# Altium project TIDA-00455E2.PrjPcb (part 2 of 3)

## Sheet Deserializer.SchDoc: Deserializer
size 431 x 279 mm; Date: Not shown in title block; ApprovedBy: Not shown in title block; CheckedBy: Not shown in title block; Author: Not shown in title block; CompanyName: Not shown in title block; DrawnBy: Brian Shaffer; Engineer: Not shown in title block; Organization: Not shown in title block; Address1: Not shown in title block; Address2: Not shown in title block; Address3: Not shown in title block; Address4: Not shown in title block; DocumentNumber: 5; Revision: Use project parameter SCH_Rev; SheetNumber: 5; SheetTotal: 10; PageSetup: Record=PageOptions¦CenterHorizontal=True¦CenterVertical=True¦PrintScale=0.96¦XCorrection=1.00¦YCorrection=1.00¦PrintKind=0¦BorderSize=5000000¦LeftOffset=0¦BottomOffset=0¦Orientation=2¦PaperLength=1000¦PaperWidth=1000¦Scale=100¦PaperSource=15¦PrintQuality=600¦MediaType=1¦DitherType=10¦PrintScaleMode=1¦PaperKind=Tabloid (11 x 17")¦PaperIndex=17
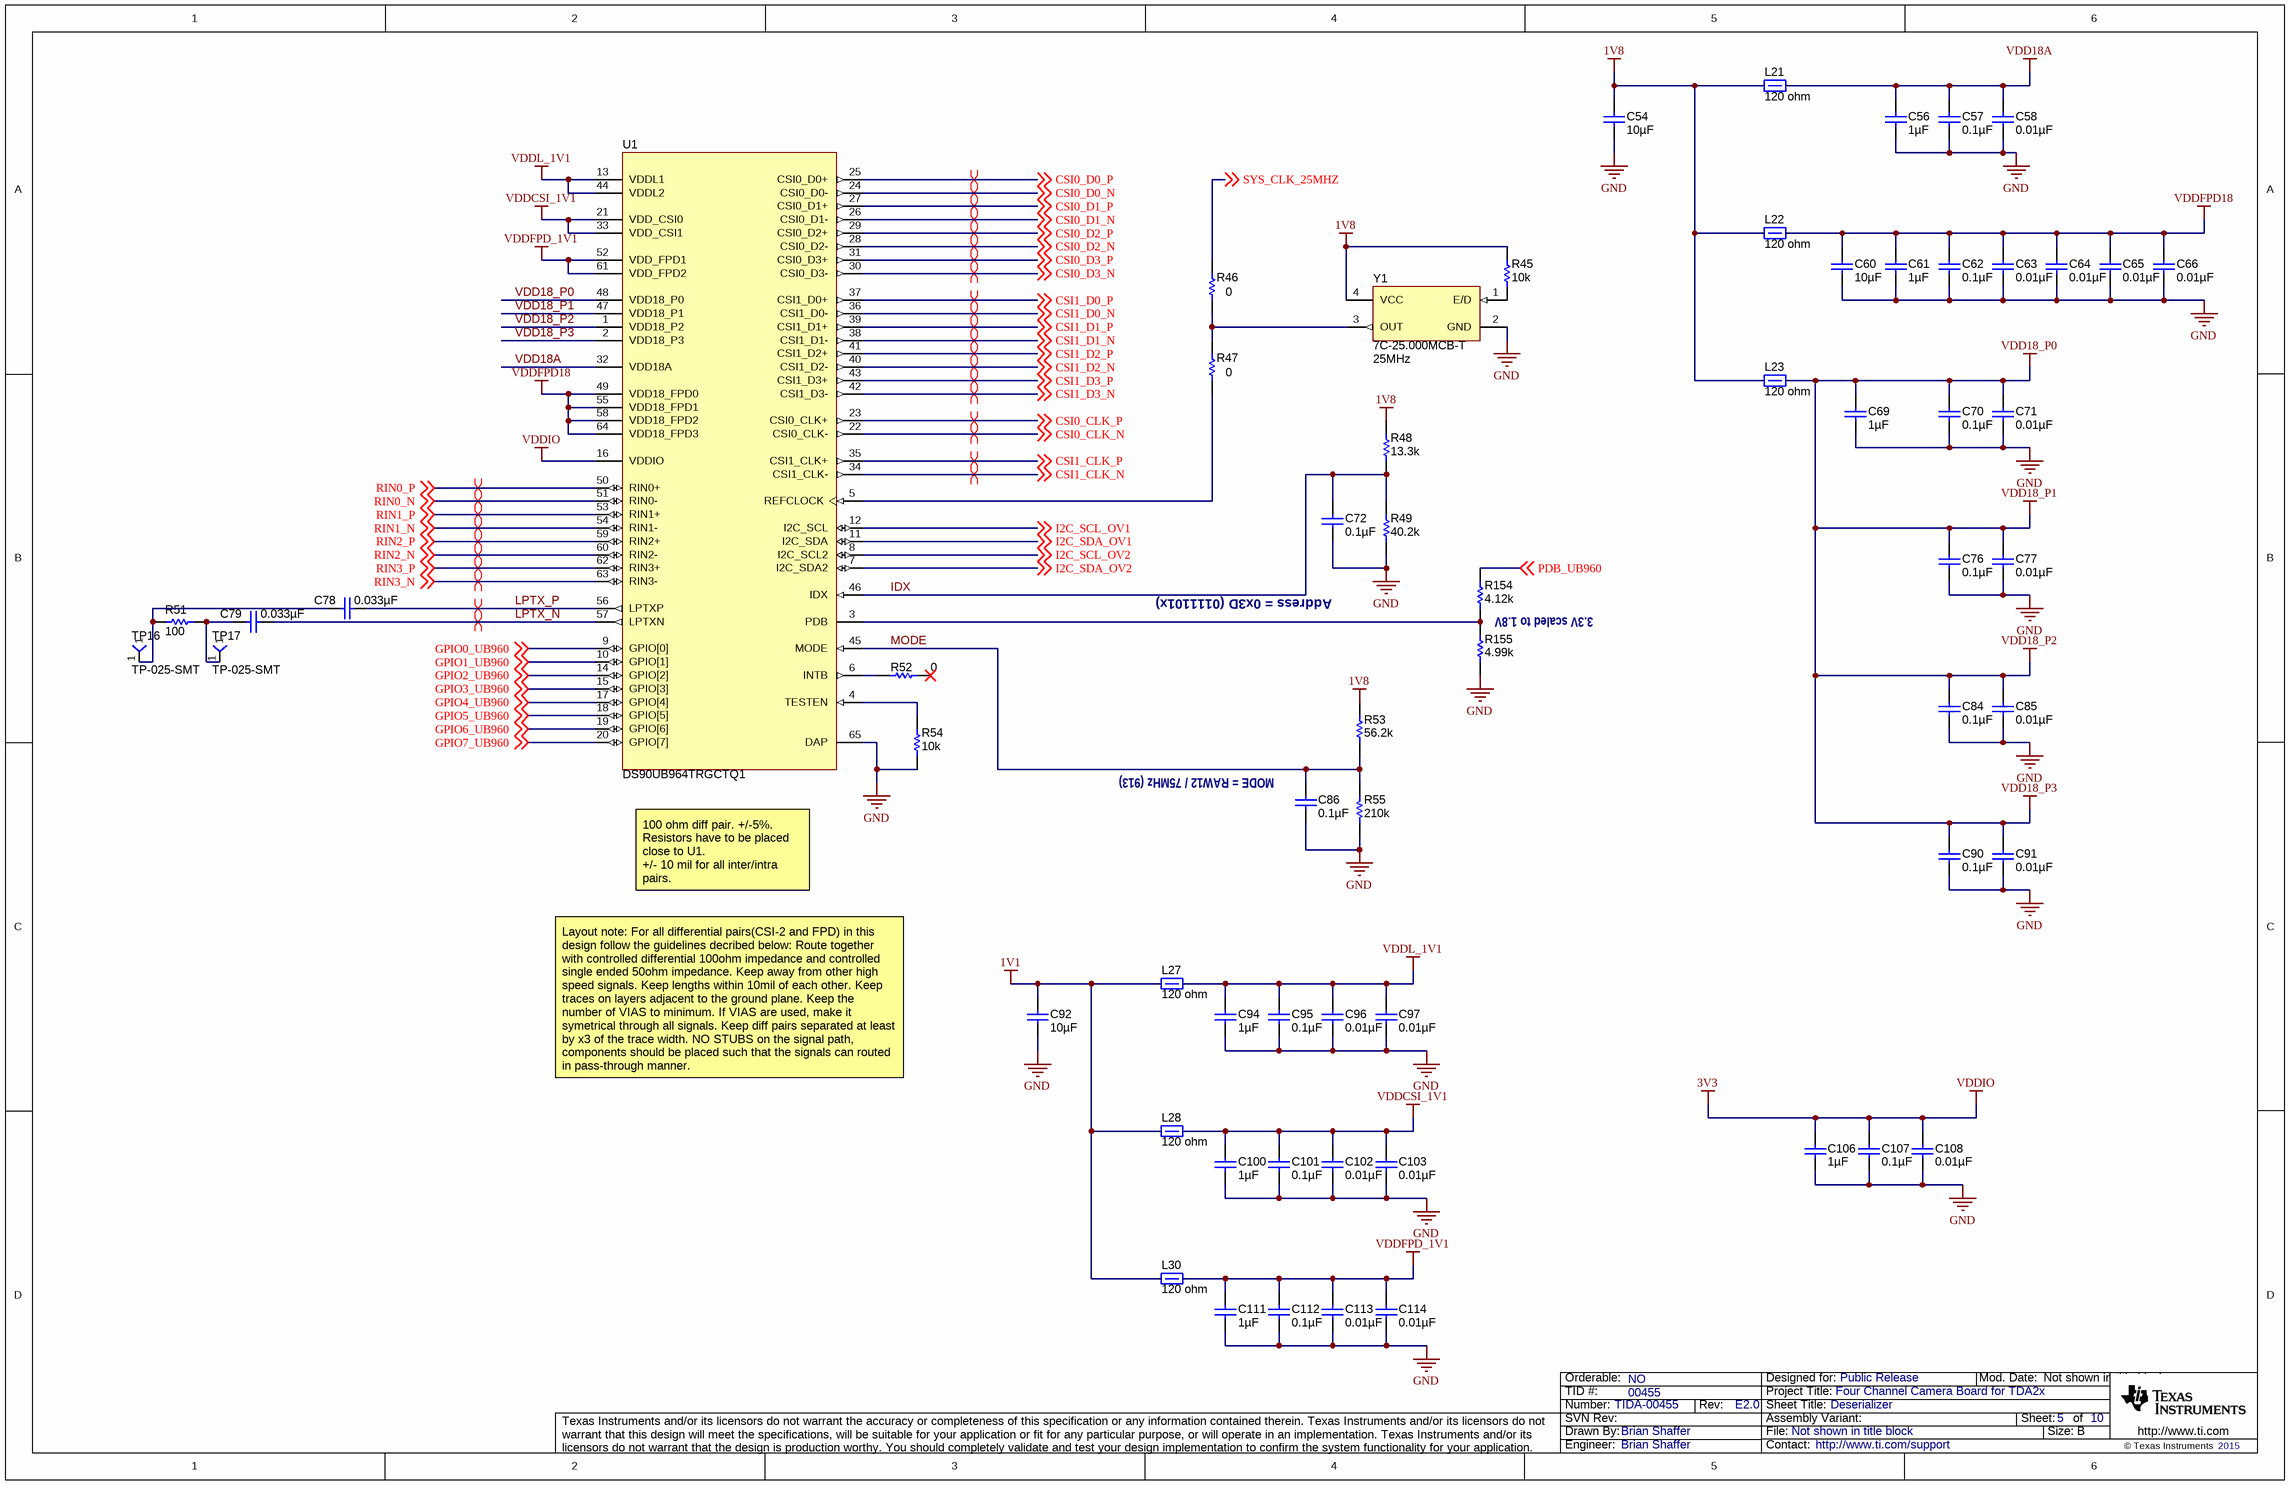
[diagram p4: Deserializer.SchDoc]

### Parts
C54  ValueDisplayed: 10µF  [0805_HV]  (hidden comment: CL21A106KAFN3NE)
C56  ValueDisplayed: 1µF  [0402]  (hidden comment: C1005JB1V105K050BC)
C57  ValueDisplayed: 0.1µF  [0603]  (hidden comment: CGA2B3X7R1H104K050BB)
C58  ValueDisplayed: 0.01µF  [0402]  (hidden comment: GCM155R71H103KA55D)
C60  ValueDisplayed: 10µF  [0805_HV]  (hidden comment: CL21A106KAFN3NE)
C61  ValueDisplayed: 1µF  [0402]  (hidden comment: C1005JB1V105K050BC)
C62  ValueDisplayed: 0.1µF  [0603]  (hidden comment: CGA2B3X7R1H104K050BB)
C63  ValueDisplayed: 0.01µF  [0402]  (hidden comment: GCM155R71H103KA55D)
C64  ValueDisplayed: 0.01µF  [0402]  (hidden comment: GCM155R71H103KA55D)
C65  ValueDisplayed: 0.01µF  [0402]  (hidden comment: GCM155R71H103KA55D)
C66  ValueDisplayed: 0.01µF  [0402]  (hidden comment: GCM155R71H103KA55D)
C69  ValueDisplayed: 1µF  [0402]  (hidden comment: C1005JB1V105K050BC)
C70  ValueDisplayed: 0.1µF  [0603]  (hidden comment: CGA2B3X7R1H104K050BB)
C71  ValueDisplayed: 0.01µF  [0402]  (hidden comment: GCM155R71H103KA55D)
C72  ValueDisplayed: 0.1µF  [0402]  (hidden comment: C1005X7R1H104M)
C76  ValueDisplayed: 0.1µF  [0603]  (hidden comment: CGA2B3X7R1H104K050BB)
C77  ValueDisplayed: 0.01µF  [0402]  (hidden comment: GCM155R71H103KA55D)
C78  ValueDisplayed: 0.033µF  [0402]  (hidden comment: CGA2B3X7R1H333K050BB)
C79  ValueDisplayed: 0.033µF  [0402]  (hidden comment: CGA2B3X7R1H333K050BB)
C84  ValueDisplayed: 0.1µF  [0603]  (hidden comment: CGA2B3X7R1H104K050BB)
C85  ValueDisplayed: 0.01µF  [0402]  (hidden comment: GCM155R71H103KA55D)
C86  ValueDisplayed: 0.1µF  [0402]  (hidden comment: C1005X7R1H104M)
C90  ValueDisplayed: 0.1µF  [0603]  (hidden comment: CGA2B3X7R1H104K050BB)
C91  ValueDisplayed: 0.01µF  [0402]  (hidden comment: GCM155R71H103KA55D)
C92  ValueDisplayed: 10µF  [0805_HV]  (hidden comment: CL21A106KAFN3NE)
C94  ValueDisplayed: 1µF  [0402]  (hidden comment: C1005JB1V105K050BC)
C95  ValueDisplayed: 0.1µF  [0603]  (hidden comment: CGA2B3X7R1H104K050BB)
C96  ValueDisplayed: 0.01µF  [0402]  (hidden comment: GCM155R71H103KA55D)
C97  ValueDisplayed: 0.01µF  [0402]  (hidden comment: GCM155R71H103KA55D)
C100  ValueDisplayed: 1µF  [0402]  (hidden comment: C1005JB1V105K050BC)
C101  ValueDisplayed: 0.1µF  [0603]  (hidden comment: CGA2B3X7R1H104K050BB)
C102  ValueDisplayed: 0.01µF  [0402]  (hidden comment: GCM155R71H103KA55D)
C103  ValueDisplayed: 0.01µF  [0402]  (hidden comment: GCM155R71H103KA55D)
C106  ValueDisplayed: 1µF  [0402]  (hidden comment: C1005JB1V105K050BC)
C107  ValueDisplayed: 0.1µF  [0603]  (hidden comment: CGA2B3X7R1H104K050BB)
C108  ValueDisplayed: 0.01µF  [0402]  (hidden comment: GCM155R71H103KA55D)
C111  ValueDisplayed: 1µF  [0402]  (hidden comment: C1005JB1V105K050BC)
C112  ValueDisplayed: 0.1µF  [0603]  (hidden comment: CGA2B3X7R1H104K050BB)
C113  ValueDisplayed: 0.01µF  [0402]  (hidden comment: GCM155R71H103KA55D)
C114  ValueDisplayed: 0.01µF  [0402]  (hidden comment: GCM155R71H103KA55D)
L21  value 120 ohm  [0603]  (hidden comment: BLM18SG121TN1D)
L22  value 120 ohm  [0603]  (hidden comment: BLM18SG121TN1D)
L23  value 120 ohm  [0603]  (hidden comment: BLM18SG121TN1D)
L27  value 120 ohm  [0603]  (hidden comment: BLM18SG121TN1D)
L28  value 120 ohm  [0603]  (hidden comment: BLM18SG121TN1D)
L30  value 120 ohm  [0603]  (hidden comment: BLM18SG121TN1D)
R45  value 10k  [0402]  (hidden comment: CRCW040210K0JNED)
R46  ValueDisplayed: 0  [0402]  (hidden comment: ERJ-2GE0R00X)
R47  ValueDisplayed: 0  [0402]  (hidden comment: ERJ-2GE0R00X)
R48  ValueDisplayed: 13.3k  [0402]  (hidden comment: CRCW040213K3FKED)
R49  ValueDisplayed: 40.2k  [0402]  (hidden comment: CRCW040240K2FKED)
R51  value 100  [0402]  (hidden comment: CRCW0402100RFKED)
R52  value 0  [0402]  (hidden comment: ERJ-2GE0R00X)
R53  ValueDisplayed: 56.2k  [0402]  (hidden comment: CRCW040256K2FKED)
R54  value 10k  [0402]  (hidden comment: CRCW040210K0JNED)
R55  ValueDisplayed: 210k  [0402]  (hidden comment: CRCW0402210KFKED)
R154  ValueDisplayed: 4.12k  [0402]  (hidden comment: CRCW04024K12FKED)
R155  ValueDisplayed: 4.99k  [0402]  (hidden comment: CRCW04024K99FKED)
TP16  TP-025-SMT  [TP_25MIL-SMT]
TP17  TP-025-SMT  [TP_25MIL-SMT]
U1  DS90UB964TRGCTQ1  [RTD0064E]
Y1  7C-25.000MCB-T  Frequency: 25MHz  [TXC_7C]

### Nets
1V1: C92.1 L27.1 L28.1 L30.1
1V8: C54.1 L21.1 L22.1 L23.1 R45.1 R48.2 R53.2 Y1.4(VCC)
3V3: C106.1 C107.1 C108.1 U1.16(VDDIO)  [also labelled VDDIO]
GND: C54.2 C56.2 C57.2 C58.2 C60.2 C61.2 C62.2 C63.2 C64.2 C65.2 C66.2 C69.2 C70.2 C71.2 C72.2 C76.2 C77.2 C84.2 C85.2 C86.2 C90.2 C91.2 C92.2 C94.2 C95.2 C96.2 C97.2 C100.2 C101.2 C102.2 C103.2 C106.2 C107.2 C108.2 C111.2 C112.2 C113.2 C114.2 R49.1 R54.1 R55.1 R155.1 U1.65(DAP) Y1.2(GND)
VDD18_P0: C69.1 C70.1 C71.1 C76.1 C77.1 C84.1 C85.1 C90.1 C91.1 L23.2 U1.1(VDD18_P2) U1.2(VDD18_P3) U1.47(VDD18_P1) U1.48(VDD18_P0)  [also labelled VDD18_P1, VDD18_P2, VDD18_P3]
VDD18A: C56.1 C57.1 C58.1 L21.2 U1.32(VDD18A)
VDDCSI_1V1: C100.1 C101.1 C102.1 C103.1 L28.2 U1.21(VDD_CSI0) U1.33(VDD_CSI1)
VDDFPD18: C60.1 C61.1 C62.1 C63.1 C64.1 C65.1 C66.1 L22.2 U1.49(VDD18_FPD0) U1.55(VDD18_FPD1) U1.58(VDD18_FPD2) U1.64(VDD18_FPD3)
VDDFPD_1V1: C111.1 C112.1 C113.1 C114.1 L30.2 U1.52(VDD_FPD1) U1.61(VDD_FPD2)
VDDL_1V1: C94.1 C95.1 C96.1 C97.1 L27.2 U1.13(VDDL1) U1.44(VDDL2)
CSI0_CLK_N: U1.22(CSI0_CLK-) ; off-sheet CSI0_CLK_N
CSI0_CLK_P: U1.23(CSI0_CLK+) ; off-sheet CSI0_CLK_P
CSI0_D0_N: U1.24(CSI0_D0-) ; off-sheet CSI0_D0_N
CSI0_D0_P: U1.25(CSI0_D0+) ; off-sheet CSI0_D0_P
CSI0_D1_N: U1.26(CSI0_D1-) ; off-sheet CSI0_D1_N
CSI0_D1_P: U1.27(CSI0_D1+) ; off-sheet CSI0_D1_P
CSI0_D2_N: U1.28(CSI0_D2-) ; off-sheet CSI0_D2_N
CSI0_D2_P: U1.29(CSI0_D2+) ; off-sheet CSI0_D2_P
CSI0_D3_N: U1.30(CSI0_D3-) ; off-sheet CSI0_D3_N
CSI0_D3_P: U1.31(CSI0_D3+) ; off-sheet CSI0_D3_P
CSI1_CLK_N: U1.34(CSI1_CLK-) ; off-sheet CSI1_CLK_N
CSI1_CLK_P: U1.35(CSI1_CLK+) ; off-sheet CSI1_CLK_P
CSI1_D0_N: U1.36(CSI1_D0-) ; off-sheet CSI1_D0_N
CSI1_D0_P: U1.37(CSI1_D0+) ; off-sheet CSI1_D0_P
CSI1_D1_N: U1.38(CSI1_D1-) ; off-sheet CSI1_D1_N
CSI1_D1_P: U1.39(CSI1_D1+) ; off-sheet CSI1_D1_P
CSI1_D2_N: U1.40(CSI1_D2-) ; off-sheet CSI1_D2_N
CSI1_D2_P: U1.41(CSI1_D2+) ; off-sheet CSI1_D2_P
CSI1_D3_N: U1.42(CSI1_D3-) ; off-sheet CSI1_D3_N
CSI1_D3_P: U1.43(CSI1_D3+) ; off-sheet CSI1_D3_P
GPIO0_UB960: U1.9(GPIO[0]) ; off-sheet GPIO0_UB960
GPIO1_UB960: U1.10(GPIO[1]) ; off-sheet GPIO1_UB960
GPIO2_UB960: U1.14(GPIO[2]) ; off-sheet GPIO2_UB960
GPIO3_UB960: U1.15(GPIO[3]) ; off-sheet GPIO3_UB960
GPIO4_UB960: U1.17(GPIO[4]) ; off-sheet GPIO4_UB960
GPIO5_UB960: U1.18(GPIO[5]) ; off-sheet GPIO5_UB960
GPIO6_UB960: U1.19(GPIO[6]) ; off-sheet GPIO6_UB960
GPIO7_UB960: U1.20(GPIO[7]) ; off-sheet GPIO7_UB960
I2C_SCL_OV1: U1.12(I2C_SCL) ; off-sheet I2C_SCL_OV1
I2C_SCL_OV2: U1.8(I2C_SCL2) ; off-sheet I2C_SCL_OV2
I2C_SDA_OV1: U1.11(I2C_SDA) ; off-sheet I2C_SDA_OV1
I2C_SDA_OV2: U1.7(I2C_SDA2) ; off-sheet I2C_SDA_OV2
IDX: C72.1 R48.1 R49.2 U1.46(IDX)
LPTX_N: C79.1 U1.57(LPTXN)
LPTX_P: C78.1 U1.56(LPTXP)
MODE: C86.1 R53.1 R55.2 U1.45(MODE)
PDB_UB960: R154.2 ; off-sheet PDB_UB960
RIN0_N: U1.51(RIN0-) ; off-sheet RIN0_N
RIN0_P: U1.50(RIN0+) ; off-sheet RIN0_P
RIN1_N: U1.54(RIN1-) ; off-sheet RIN1_N
RIN1_P: U1.53(RIN1+) ; off-sheet RIN1_P
RIN2_N: U1.60(RIN2-) ; off-sheet RIN2_N
RIN2_P: U1.59(RIN2+) ; off-sheet RIN2_P
RIN3_N: U1.63(RIN3-) ; off-sheet RIN3_N
RIN3_P: U1.62(RIN3+) ; off-sheet RIN3_P
SYS_CLK_25MHZ: R46.2 ; off-sheet SYS_CLK_25MHZ
NetC78_2: C78.2 R51.2 TP16.1
NetC79_2: C79.2 R51.1 TP17.1
NetR45_2: R45.2 Y1.1(E/D)
NetR46_1: R46.1 R47.2 Y1.3(OUT)
NetR47_1: R47.1 U1.5(REFCLOCK)
NetR52_1: R52.1 U1.6(INTB)
NetR54_2: R54.2 U1.4(TESTEN)
NetR154_1: R154.1 R155.2 U1.3(PDB)

Not connected (* = marked no-connect by the designer): R52 2*

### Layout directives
differential pair: CSI0_CLK_N, CSI0_CLK_P, CSI0_D0_N, CSI0_D0_P, CSI0_D1_N, CSI0_D1_P, CSI0_D2_N, CSI0_D2_P, CSI0_D3_N, CSI0_D3_P, CSI1_CLK_N, CSI1_CLK_P, CSI1_D0_N, CSI1_D0_P, CSI1_D1_N, CSI1_D1_P, CSI1_D2_N, CSI1_D2_P, CSI1_D3_N, CSI1_D3_P, LPTX_N, LPTX_P, RIN0_N, RIN0_P, RIN1_N, RIN1_P, RIN2_N, RIN2_P, RIN3_N, RIN3_P

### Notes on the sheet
- Address = 0x3D (0111101x)
- 3.3V scaled to 1.8V
- (near C86) MODE = RAW12 / 75MHz (913)
- 100 ohm diff pair. +/-5%.
  Resistors have to be placed close to U1.
  +/- 10 mil for all inter/intra pairs.
- Layout note: For all differential pairs(CSI-2 and FPD) in this design follow the guidelines decribed below: Route together with controlled differential 100ohm impedance and controlled single ended 50ohm impedance. Keep away from other high speed signals. Keep lengths within 10mil of each other. Keep traces on layers adjacent to the ground plane. Keep the number of VIAS to minimum. If VIAS are used, make it symetrical through all signals. Keep diff pairs separated at least by x3 of the trace width. NO STUBS on the signal path, components should be placed such that the signals can routed in pass-through manner.

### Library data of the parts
C54 C60 C92 = CL21A106KAFN3NE: CAP, CERM, 10 µF, 25 V, +/- 10%, X5R, 0805; Manufacturer: Samsung; Polarized: N; CompType: Capacitor; Value: 10uF; U/M: EA; Cap_F: 0.00001; Tolerance_%: 10; Value1: Unknown; VDC_V: 25; Value2: 25V; TaMin_C: -55; TaMax_C: 85; Cap_Case: 0805
C56 C61 C69 C94 C100 C106 C111 = C1005JB1V105K050BC: CAP, CERM, 1 µF, 35 V, +/- 10%, JB, 0402; Manufacturer: TDK; Polarized: N; CompType: Capacitor; Value: 1uF; U/M: EA; Cap_F: 0.000001; Tolerance_%: 10; Value1: Unknown; VDC_V: 35; Value2: 35V; TaMin_C: -25; TaMax_C: 85
C57 C62 C70 C76 C84 C90 C95 C101 C107 C112 = GRM188R71C474KA88D: CAP, CERM, 0.1uF, 50V, +/-10%, X7R, 0402; Manufacturer: TDK; Polarized: N; CompType: Capacitor; U/M: EA; Cap_F: 0.00000001; Tolerance_%: 10; Value1: Unknown; TaMin_C: -55; TaMax_C: 125; Cap_Case: 0402
C58 C63-C66 C71 C77 C85 C91 C96 C97 C102 C103 C108 C113 C114 = GCM155R71H103KA55D: CAP, CERM, 0.01uF, 50V, +/-10%, C0G/NP0, 0402; Manufacturer: MuRata; Polarized: N; CompType: Capacitor; U/M: EA; Cap_F: 0.00000001; Tolerance_%: 10; Value1: Unknown; VDC_V: 50; TaMin_C: -55; TaMax_C: 125
C72 C86 = C1005X7R1H104M: CAP, CERM, 0.1uF, 50V, +/-20%, C0G/NP0, 0402; Manufacturer: TDK; Polarized: N; CompType: Capacitor; U/M: EA; Cap_F: 0.0000001; Tolerance_%: 20; Value1: Unknown; VDC_V: 50; TaMin_C: -55; TaMax_C: 125
C78 C79 = CGA2B3X7R1H333K050BB: CAP, CERM, 0.033 µF, 50 V, +/- 10%, X7R, 0402; Manufacturer: TDK; Polarized: N; CompType: Capacitor; Value: 0.033uF; U/M: EA; Cap_F: 0.000000033; Tolerance_%: 10; Value1: Unknown; VDC_V: 50; Value2: 50V; TaMin_C: -55; TaMax_C: 125
L21 = BLM18SG121TN1D: Ferrite Bead, 120 ohm @ 100 MHz, 3 A, 0603; Manufacturer: MuRata; Imax_A: 3; DCR_ohm: 0.025; Value1: 0.025 ohm; Value2: 3A; ZTyp@100MHz_Ohm: 120
L22 L23 L27 L28 L30 = BLM18SG331TN1D: 1.5A Ferrite Bead, 330 ohm @ 100MHz, SMD; Manufacturer: MuRata; Imax_A: 3; DCR_ohm: 25milliiohm; Value1: 25 milliohm; Value2: 3A; ZTyp@100MHz_Ohm: 120; U/M: EA
R45 R54 = CRCW040210K0JNED: RES, 10k ohm, 5%, 0.063W, 0402; Manufacturer: Vishay-Dale; CompType: Resistor; Res_ohm: 10000; Value_Code: 10k0; Tolerance_%: 5; Power_W: 0.063; VDC_V: 50; TempCo: 200 ppm/C; EIA_Code: E24; U/M: EA
R46 R47 = ERJ-2GE0R00X: RES, 0, 5%, 0.063 W, 0402; Manufacturer: Panasonic; CompType: Resistor; Value: 0; Value_Code: 0000; Tolerance_%: 5; Power_W: 0.063; Value2: 0.063W; VDC_V: 50; TempCo: 600 ppm/C; EIA_Code: E24; U/M: EA
R48 = CRCW040213K3FKED: RES, 13.3 k, 1%, 0.063 W, 0402; Manufacturer: Vishay-Dale; CompType: Resistor; Value: 13.3k; Res_ohm: 13300; Value_Code: 13k3; Tolerance_%: 1; Power_W: 0.063; Value2: 0.063W; VDC_V: 50; TempCo: 100 ppm/C; EIA_Code: E96; U/M: EA
R49 = CRCW040240K2FKED: RES, 40.2 k, 1%, 0.063 W, 0402; Manufacturer: Vishay-Dale; CompType: Resistor; Value: 40.2k; Res_ohm: 40200; Value_Code: 40k2; Tolerance_%: 1; Power_W: 0.063; Value2: 0.063W; VDC_V: 50; TempCo: 100 ppm/C; EIA_Code: E96; U/M: EA
R51 = CRCW0402100RFKED: RES, 100 ohm, 1%, 0.063W, 0402; Manufacturer: Vishay-Dale; CompType: Resistor; Value_Code: 100R; Tolerance_%: 1; Power_W: 0.063; VDC_V: 50; TempCo: 100 ppm/C; EIA_Code: E96; U/M: EA
R52 = ERJ-2GE0R00X: RES, 0 ohm, 5%, 0.063W, 0402; Manufacturer: Panasonic; CompType: Resistor; Value_Code: 0000; Tolerance_%: 5; Power_W: 0.063; VDC_V: 50; TempCo: 600 ppm/C; EIA_Code: E24; U/M: EA
R53 = CRCW040256K2FKED: RES, 56.2 k, 1%, 0.063 W, 0402; Manufacturer: Vishay-Dale; CompType: Resistor; Value: 56.2k; Res_ohm: 56200; Value_Code: 56k2; Tolerance_%: 1; Power_W: 0.063; Value2: 0.063W; VDC_V: 50; TempCo: 100 ppm/C; EIA_Code: E96; U/M: EA
R55 = CRCW0402210KFKED: RES, 210 k, 1%, 0.063 W, 0402; Manufacturer: Vishay-Dale; CompType: Resistor; Value: 210k; Res_ohm: 210000; Tolerance_%: 1; Power_W: 0.063; Value2: 0.063W; VDC_V: 50; TempCo: 100 ppm/C; EIA_Code: E96; U/M: EA
R154 = CRCW04024K12FKED: RES, 4.12 k, 1%, 0.063 W, 0402; Manufacturer: Vishay-Dale; CompType: Resistor; Value: 4.12k; Res_ohm: 4120; Value_Code: 4k12; Tolerance_%: 1; Power_W: 0.063; Value2: 0.063W; VDC_V: 50; TempCo: 100 ppm/C; EIA_Code: E96; U/M: EA
R155 = CRCW04024K99FKED: RES, 4.99 k, 1%, 0.063 W, 0402; Manufacturer: Vishay-Dale; CompType: Resistor; Value: 4.99k; Res_ohm: 4990; Value_Code: 4k99; Tolerance_%: 1; Power_W: 0.063; Value2: 0.063W; VDC_V: 50; TempCo: 100 ppm/C; EIA_Code: E96; U/M: EA
TP16 TP17 = TP-025-SMT: Test Point, O.025"; Manufacturer: STD; Value: STD
U1 = DS90UB960QRTD: FPD-Link III Camera Hub Deserializer, RTD0064E; PartNumber: DS90UB964QRTD; Alternate Manufacturer: None; Manufacturer: Texas Instruments; SymbolCreator: Altium; CompType: IC; U/M: EA
Y1 = 7C-25.000MCB-T: XO, 25.000MHz, 2.5V, SMD; Manufacturer: TXC Corporation; SymbolCreator: a0411947; CompType: Oscillator; U/M: EA; TaMin_C: -40; TaMax_C: 85; Frequency Stability: ±50ppm

## Sheet OV490_1.SchDoc: OV490_1
size 431 x 279 mm; Date: Not shown in title block; ApprovedBy: Not shown in title block; CheckedBy: Not shown in title block; Author: Not shown in title block; CompanyName: Not shown in title block; DrawnBy: Brian Shaffer; Engineer: Not shown in title block; Organization: Not shown in title block; Address1: Not shown in title block; Address2: Not shown in title block; Address3: Not shown in title block; Address4: Not shown in title block; DocumentNumber: 6; Revision: Use project parameter SCH_Rev; SheetNumber: 6; SheetTotal: 10; PageSetup: Record=PageOptions¦CenterHorizontal=True¦CenterVertical=True¦PrintScale=1.00¦XCorrection=1.00¦YCorrection=1.00¦PrintKind=0¦BorderSize=5000000¦LeftOffset=0¦BottomOffset=0¦Orientation=2¦PaperLength=1000¦PaperWidth=1000¦Scale=100¦PaperSource=15¦PrintQuality=600¦MediaType=1¦DitherType=10¦PaperKind=Letter¦PrintScaleMode=1
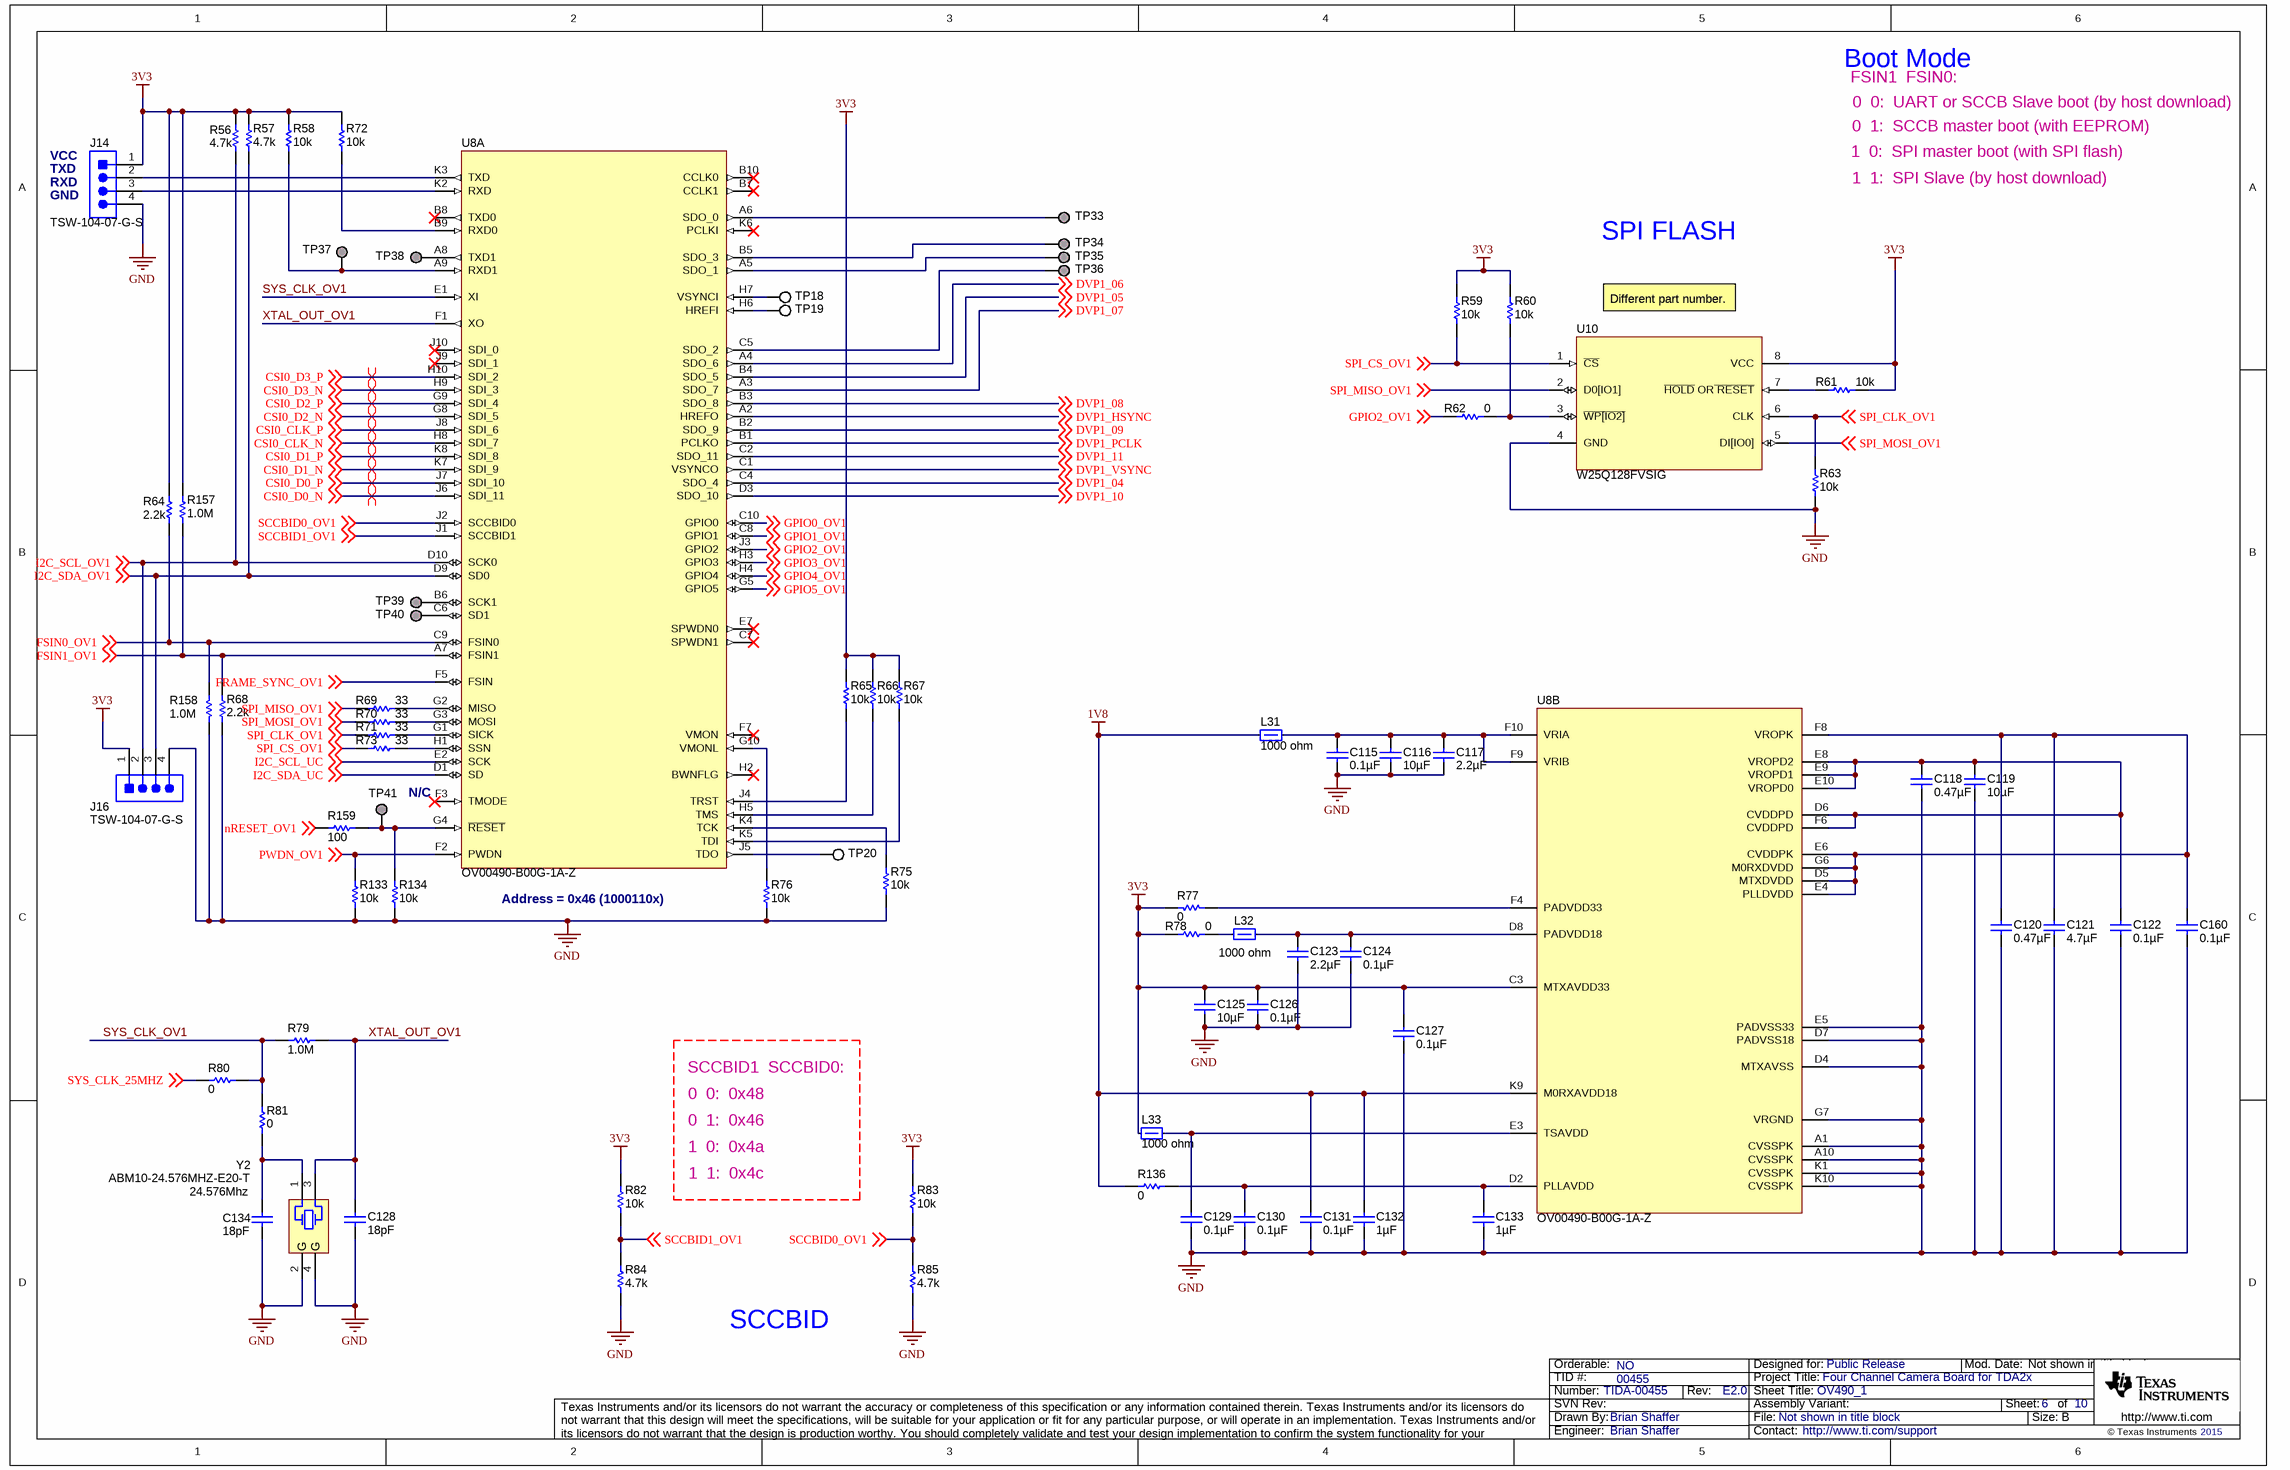
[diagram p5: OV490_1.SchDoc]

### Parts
C115  ValueDisplayed: 0.1µF  [0402]  (hidden comment: C1005X7R1H104K050BB)
C116  ValueDisplayed: 10µF  [0805]  (hidden comment: C2012X7R0J106M125AB)
C117  ValueDisplayed: 2.2µF  [0603]  (hidden comment: C0603C225M8PACTU)
C118  ValueDisplayed: 0.47µF  [0402]  (hidden comment: C1005X5R1A474K050BB)
C119  ValueDisplayed: 10µF  [0805]  (hidden comment: C2012X7R0J106M125AB)
C120  ValueDisplayed: 0.47µF  [0402]  (hidden comment: C1005X5R1A474K050BB)
C121  ValueDisplayed: 4.7µF  [0402]  (hidden comment: C1005X5R1A475K050BC)
C122  ValueDisplayed: 0.1µF  [0402]  (hidden comment: C1005X7R1H104K050BB)
C123  ValueDisplayed: 2.2µF  [0805]  (hidden comment: C2012X5R1A225K/0.85)
C124  ValueDisplayed: 0.1µF  [0402]  (hidden comment: C1005X7R1H104K050BB)
C125  ValueDisplayed: 10µF  [0805]  (hidden comment: C2012X7R0J106M125AB)
C126  ValueDisplayed: 0.1µF  [0402]  (hidden comment: C1005X7R1H104K050BB)
C127  ValueDisplayed: 0.1µF  [0402]  (hidden comment: C1005X7R1H104K050BB)
C128  ValueDisplayed: 18pF  [0603]  (hidden comment: GRM1885C2A180JA01D)
C129  ValueDisplayed: 0.1µF  [0402]  (hidden comment: C1005X7R1H104K050BB)
C130  ValueDisplayed: 0.1µF  [0402]  (hidden comment: C1005X7R1H104K050BB)
C131  ValueDisplayed: 0.1µF  [0402]  (hidden comment: C1005X7R1H104K050BB)
C132  ValueDisplayed: 1µF  [0603]  (hidden comment: C0603C105K4PACTU)
C133  ValueDisplayed: 1µF  [0603]  (hidden comment: C0603C105K4PACTU)
C134  ValueDisplayed: 18pF  [0603]  (hidden comment: GRM1885C2A180JA01D)
C160  ValueDisplayed: 0.1µF  [0402]  (hidden comment: C1005X7R1H104K050BB)
J14  TSW-104-07-G-S  [TSW-104-07-G-S]
J16  TSW-104-07-G-S  [TSW-104-07-G-S]
L31  value 1000 ohm  [0805_HV]  (hidden comment: BK2125HS102-T)
L32  value 1000 ohm  [0805_HV]  (hidden comment: BK2125HS102-T)
L33  value 1000 ohm  [0805_HV]  (hidden comment: BK2125HS102-T)
R56  ValueDisplayed: 4.7k  [0402]  (hidden comment: CRCW04024K70JNED)
R57  ValueDisplayed: 4.7k  [0402]  (hidden comment: CRCW04024K70JNED)
R58  ValueDisplayed: 10k  [0402]  (hidden comment: CRCW040210K0JNED)
R59  ValueDisplayed: 10k  [0402]  (hidden comment: CRCW040210K0JNED)
R60  ValueDisplayed: 10k  [0402]  (hidden comment: CRCW040210K0JNED)
R61  ValueDisplayed: 10k  [0402]  (hidden comment: CRCW040210K0JNED)
R62  ValueDisplayed: 0  [0402]  (hidden comment: CRCW04020000Z0ED)
R63  ValueDisplayed: 10k  [0402]  (hidden comment: CRCW040210K0JNED)
R64  ValueDisplayed: 2.2k  [0402]  (hidden comment: CRCW04022K20JNED)
R65  ValueDisplayed: 10k  [0402]  (hidden comment: CRCW040210K0JNED)
R66  ValueDisplayed: 10k  [0402]  (hidden comment: CRCW040210K0JNED)
R67  ValueDisplayed: 10k  [0402]  (hidden comment: CRCW040210K0JNED)
R68  ValueDisplayed: 2.2k  [0402]  (hidden comment: CRCW04022K20JNED)
R69  ValueDisplayed: 33  [0402]  (hidden comment: CRCW040233R0JNED)
R70  ValueDisplayed: 33  [0402]  (hidden comment: CRCW040233R0JNED)
R71  ValueDisplayed: 33  [0402]  (hidden comment: CRCW040233R0JNED)
R72  ValueDisplayed: 10k  [0402]  (hidden comment: CRCW040210K0JNED)
R73  ValueDisplayed: 33  [0402]  (hidden comment: CRCW040233R0JNED)
R75  ValueDisplayed: 10k  [0402]  (hidden comment: CRCW040210K0JNED)
R76  ValueDisplayed: 10k  [0402]  (hidden comment: CRCW040210K0JNED)
R77  ValueDisplayed: 0  [0402]  (hidden comment: CRCW04020000Z0ED)
R78  value 0  [0402]  (hidden comment: ERJ-2GE0R00X)
R79  ValueDisplayed: 1.0M  [0402]  (hidden comment: CRCW04021M00JNED)
R80  ValueDisplayed: 0  [0402]  (hidden comment: CRCW04020000Z0ED)
R81  ValueDisplayed: 0  [0402]  (hidden comment: CRCW04020000Z0ED)
R82  ValueDisplayed: 10k  [0402]  (hidden comment: CRCW040210K0JNED)
R83  ValueDisplayed: 10k  [0402]  (hidden comment: CRCW040210K0JNED)
R84  ValueDisplayed: 4.7k  [0402]  (hidden comment: CRCW04024K70JNED)
R85  ValueDisplayed: 4.7k  [0402]  (hidden comment: CRCW04024K70JNED)
R133  ValueDisplayed: 10k  [0402]  (hidden comment: CRCW040210K0JNED)
R134  ValueDisplayed: 10k  [0402]  (hidden comment: CRCW040210K0JNED)
R136  value 0  [0805_HV]  (hidden comment: CRCW08050000Z0EA)
R157  ValueDisplayed: 1.0M  [0402]  (hidden comment: CRCW04021M00JNED)
R158  ValueDisplayed: 1.0M  [0402]  (hidden comment: CRCW04021M00JNED)
R159  value 100  [0402]  (hidden comment: CRCW0402100RFKED)
TP18  5015  [Testpoint_Keystone_Miniature]  (value not drawn)
TP19  5015  [Testpoint_Keystone_Miniature]  (value not drawn)
TP20  5015  [Testpoint_Keystone_Miniature]  (value not drawn)
TP33  Pogo Pad  [PogoPad]  (value not drawn)  (no BOM)
TP34  Pogo Pad  [PogoPad]  (value not drawn)  (no BOM)
TP35  Pogo Pad  [PogoPad]  (value not drawn)  (no BOM)
TP36  Pogo Pad  [PogoPad]  (value not drawn)  (no BOM)
TP37  Pogo Pad  [PogoPad]  (value not drawn)  (no BOM)
TP38  Pogo Pad  [PogoPad]  (value not drawn)  (no BOM)
TP39  Pogo Pad  [PogoPad]  (value not drawn)  (no BOM)
TP40  Pogo Pad  [PogoPad]  (value not drawn)  (no BOM)
TP41  Pogo Pad  [PogoPad]  (value not drawn)  (no BOM)
U8  OV00490-B00G-1A-Z  [OVT_OV490]  (parts A,B of 2)
U10  W25Q128FVSIG  [SOIC127P800X216-8N]
Y2  ABM10-24.576MHZ-E20-T  Frequency: 24.576Mhz  [XTAL_ABM10]

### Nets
1V8: C131.1 C132.2 L31.2 R136.1 U8.K9(M0RXAVDD18)
3V3: C125.1 C126.1 C127.2 J14.1 J16.1 L33.2 R56.2 R57.2 R58.2 R59.2 R60.2 R61.1 R64.2 R65.2 R66.2 R67.2 R72.2 R77.2 R78.1 R82.2 R83.2 R157.2 U8.C3(MTXAVDD33) U10.8(VCC)
GND: C115.2 C116.2 C117.2 C118.1 C119.1 C120.1 C121.1 C122.1 C123.1 C124.1 C125.2 C126.2 C127.1 C128.2 C129.2 C130.2 C131.2 C132.1 C133.1 C134.2 C160.1 J14.4 J16.4 R63.1 R68.1 R75.1 R76.1 R84.1 R85.1 R133.1 R134.1 R158.2 U8.A1(CVSSPK) U8.A10(CVSSPK) U8.D4(MTXAVSS) U8.D7(PADVSS18) U8.E5(PADVSS33) U8.G7(VRGND) U8.K1(CVSSPK) U8.K10(CVSSPK) U10.4(GND) Y2.2(GND) Y2.4(GND)
CSI0_CLK_N: U8.H8(SDI_7) ; off-sheet CSI0_CLK_N
CSI0_CLK_P: U8.J8(SDI_6) ; off-sheet CSI0_CLK_P
CSI0_D0_N: U8.J6(SDI_11) ; off-sheet CSI0_D0_N
CSI0_D0_P: U8.J7(SDI_10) ; off-sheet CSI0_D0_P
CSI0_D1_N: U8.K7(SDI_9) ; off-sheet CSI0_D1_N
CSI0_D1_P: U8.K8(SDI_8) ; off-sheet CSI0_D1_P
CSI0_D2_N: U8.G8(SDI_5) ; off-sheet CSI0_D2_N
CSI0_D2_P: U8.G9(SDI_4) ; off-sheet CSI0_D2_P
CSI0_D3_N: U8.H9(SDI_3) ; off-sheet CSI0_D3_N
CSI0_D3_P: U8.H10(SDI_2) ; off-sheet CSI0_D3_P
DVP1_04: U8.C4(SDO_4) ; off-sheet DVP1_04
DVP1_05: U8.B4(SDO_5) ; off-sheet DVP1_05
DVP1_06: U8.A4(SDO_6) ; off-sheet DVP1_06
DVP1_07: U8.A3(SDO_7) ; off-sheet DVP1_07
DVP1_08: U8.B3(SDO_8) ; off-sheet DVP1_08
DVP1_09: U8.B2(SDO_9) ; off-sheet DVP1_09
DVP1_10: U8.D3(SDO_10) ; off-sheet DVP1_10
DVP1_11: U8.C2(SDO_11) ; off-sheet DVP1_11
DVP1_HSYNC: U8.A2(HREFO) ; off-sheet DVP1_HSYNC
DVP1_PCLK: U8.B1(PCLKO) ; off-sheet DVP1_PCLK
DVP1_VSYNC: U8.C1(VSYNCO) ; off-sheet DVP1_VSYNC
FRAME_SYNC_OV1: U8.F5(FSIN) ; off-sheet FRAME_SYNC_OV1
FSIN0_OV1: R64.1 R158.1 U8.C9(FSIN0) ; off-sheet FSIN0_OV1
FSIN1_OV1: R68.2 R157.1 U8.A7(FSIN1) ; off-sheet FSIN1_OV1
GPIO0_OV1: U8.C10(GPIO0) ; off-sheet GPIO0_OV1
GPIO1_OV1: U8.C8(GPIO1) ; off-sheet GPIO1_OV1
GPIO2_OV1: R62.1 U8.J3(GPIO2) ; off-sheet GPIO2_OV1
GPIO3_OV1: U8.H3(GPIO3) ; off-sheet GPIO3_OV1
GPIO4_OV1: U8.H4(GPIO4) ; off-sheet GPIO4_OV1
GPIO5_OV1: U8.G5(GPIO5) ; off-sheet GPIO5_OV1
I2C_SCL_OV1: J16.2 R56.1 U8.D10(SCK0) ; off-sheet I2C_SCL_OV1
I2C_SCL_UC: U8.E2(SCK) ; off-sheet I2C_SCL_UC
I2C_SDA_OV1: J16.3 R57.1 U8.D9(SD0) ; off-sheet I2C_SDA_OV1
I2C_SDA_UC: U8.D1(SD) ; off-sheet I2C_SDA_UC
nRESET_OV1: R159.2 ; off-sheet nRESET_OV1
PWDN_OV1: R133.2 U8.F2(PWDN) ; off-sheet PWDN_OV1
SCCBID0_OV1: R83.1 R85.2 U8.J2(SCCBID0) ; off-sheet SCCBID0_OV1
SCCBID1_OV1: R82.1 R84.2 U8.J1(SCCBID1) ; off-sheet SCCBID1_OV1
SPI_CLK_OV1: R63.2 R71.1 U10.6(CLK) ; off-sheet SPI_CLK_OV1
SPI_CS_OV1: R59.1 R73.1 U10.1(~{CS}) ; off-sheet SPI_CS_OV1
SPI_MISO_OV1: R69.1 U10.2(D0[IO1]) ; off-sheet SPI_MISO_OV1
SPI_MOSI_OV1: R70.1 U10.5(DI[IO0]) ; off-sheet SPI_MOSI_OV1
SYS_CLK_25MHZ: R80.1 ; off-sheet SYS_CLK_25MHZ
SYS_CLK_OV1: R79.1 R80.2 R81.2 U8.E1(XI)
XTAL_OUT_OV1: C128.1 R79.2 U8.F1(XO) Y2.3
NetC115_1: C115.1 C116.1 C117.1 L31.1 U8.F9(VRIB) U8.F10(VRIA)
NetC118_2: C118.2 C119.2 C122.2 U8.D6(CVDDPD) U8.E8(VROPD2) U8.E9(VROPD1) U8.E10(VROPD0) U8.F6(CVDDPD)
NetC120_2: C120.2 C121.2 C160.2 U8.D5(MTXDVDD) U8.E4(PLLDVDD) U8.E6(CVDDPK) U8.F8(VROPK) U8.G6(M0RXDVDD)
NetC123_2: C123.2 C124.2 L32.1 U8.D8(PADVDD18)
NetC129_1: C129.1 L33.1 U8.E3(TSAVDD)
NetC130_1: C130.1 C133.2 R136.2 U8.D2(PLLAVDD)
NetC134_1: C134.1 R81.1 Y2.1
NetJ14_2: J14.2 U8.K3(TXD)
NetJ14_3: J14.3 U8.K2(RXD)
NetL32_2: L32.2 R78.2
NetR58_1: R58.1 TP37.1 U8.A9(RXD1)
NetR60_1: R60.1 R62.2 U10.3(~{WP[IO2]})
NetR61_2: R61.2 U10.7(~{HOLD}_OR~{_RESET})
NetR65_1: R65.1 U8.J4(TRST)
NetR66_1: R66.1 U8.H5(TMS)
NetR67_1: R67.1 U8.K5(TDI)
NetR69_2: R69.2 U8.G2(MISO)
NetR70_2: R70.2 U8.G3(MOSI)
NetR71_2: R71.2 U8.G1(SICK)
NetR72_1: R72.1 U8.B9(RXD0)
NetR73_2: R73.2 U8.H1(SSN)
NetR75_2: R75.2 U8.K4(TCK)
NetR76_2: R76.2 U8.G10(VMONL)
NetR77_1: R77.1 U8.F4(PADVDD33)
NetR134_2: R134.2 R159.1 TP41.1 U8.G4(~{RESET})
NetTP18_1: TP18.1 U8.H7(VSYNCI)
NetTP19_1: TP19.1 U8.H6(HREFI)
NetTP20_1: TP20.1 U8.J5(TDO)
NetTP33_1: TP33.1 U8.A6(SDO_0)
NetTP34_1: TP34.1 U8.B5(SDO_3)
NetTP35_1: TP35.1 U8.A5(SDO_1)
NetTP36_1: TP36.1 U8.C5(SDO_2)
NetTP38_1: TP38.1 U8.A8(TXD1)
NetTP39_1: TP39.1 U8.B6(SCK1)
NetTP40_1: TP40.1 U8.C6(SD1)

Not connected (* = marked no-connect by the designer): U8 B7(CCLK1)* B8(TXD0)* B10(CCLK0)* C7(SPWDN1)* E7(SPWDN0)* F3(TMODE)* F7(VMON)* H2(BWNFLG)* J9(SDI_1)* J10(SDI_0)* K6(PCLKI)*

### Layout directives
differential pair: CSI0_CLK_N, CSI0_CLK_P, CSI0_D0_N, CSI0_D0_P, CSI0_D1_N, CSI0_D1_P, CSI0_D2_N, CSI0_D2_P, CSI0_D3_N, CSI0_D3_P

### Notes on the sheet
- FSIN1  FSIN0:
- Boot Mode
- 0  0:  UART or SCCB Slave boot (by host download)
- (near J14) VCC
- 1  0:  SPI master boot (with SPI flash)
- 0  1:  SCCB master boot (with EEPROM)
- (near J14) TXD
- (near J14) RXD
- (near J14) GND
- SPI FLASH
- 1  1:  SPI Slave (by host download)
- Different part number.
- N/C
- (near U8) Address = 0x46 (1000110x)
- 0  0:  0x48
- SCCBID1  SCCBID0:
- 0  1:  0x46
- 1  0:  0x4a
- 1  1:  0x4c
- SCCBID

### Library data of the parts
C115 C122 C124 C126 C127 C129-C131 C160 = C1005X7R1H104K050BB: CAP, CERM, 0.1 µF, 50 V, +/- 10%, X7R, 0402; Manufacturer: TDK; Polarized: N; CompType: Capacitor; Value: 0.1uF; U/M: EA; Cap_F: 0.0000001; Tolerance_%: 10; Value1: Unknown; VDC_V: 50; Value2: 50V; TaMin_C: -55; TaMax_C: 125
C116 C119 C125 = C2012X7R0J106M125AB: CAP, CERM, 10 µF, 6.3 V, +/- 20%, X7R, 0805; Manufacturer: TDK; Polarized: N; CompType: Capacitor; Value: 10uF; U/M: EA; Cap_F: 0.00001; Tolerance_%: 20; Value1: Unknown; VDC_V: 6.3; Value2: 6.3V; TaMin_C: -55; TaMax_C: 125
C117 = C0603C225M8PACTU: CAP, CERM, 2.2 µF, 10 V, +/- 20%, X5R, 0603; Manufacturer: Kemet; Polarized: N; CompType: Capacitor; Value: 2.2uF; U/M: EA; Cap_F: 0.0000022; Tolerance_%: 20; Value1: Unknown; VDC_V: 10; Value2: 10V; TaMin_C: -55; TaMax_C: 85
C118 C120 = C1005X5R1A474K050BB: CAP, CERM, 0.47 µF, 10 V, +/- 10%, X5R, 0402; Manufacturer: TDK; Polarized: N; CompType: Capacitor; Value: 0.47uF; U/M: EA; Cap_F: 0.00000047; Tolerance_%: 10; Value1: Unknown; Value2: 10V; TaMin_C: -55; TaMax_C: 85
C121 = C1005X5R1A475K050BC: CAP, CERM, 4.7 µF, 10 V, +/- 10%, X5R, 0402; Manufacturer: TDK; Polarized: N; CompType: Capacitor; Value: 4.7uF; U/M: EA; Cap_F: 0.0000047; Tolerance_%: 10; Value1: Unknown; Value2: 10V; TaMin_C: -55; TaMax_C: 85
C123 = C2012X5R1A225K/0.85: CAP, CERM, 2.2 µF, 10 V, +/- 10%, X5R, 0805; Manufacturer: TDK; Polarized: N; CompType: Capacitor; Value: 2.2uF; U/M: EA; Cap_F: 0.0000022; Tolerance_%: 10; ESR_ohm: 0.0049; Value1: 0.0049 ohm; Value2: 10V; IRMS_A: 2.08; TaMin_C: -55; TaMax_C: 85
C128 C134 = GRM1885C2A180JA01D: CAP, CERM, 18 pF, 100 V, +/- 5%, C0G/NP0, 0603; Manufacturer: MuRata; Polarized: N; CompType: Capacitor; Value: 18pF; U/M: EA; Cap_F: 0.000000000018; Tolerance_%: 5; Value1: Unknown; VDC_V: 100; Value2: 100V; TaMin_C: -55; TaMax_C: 125
C132 C133 = C0603C105K4PACTU: CAP, CERM, 1 µF, 16 V, +/- 10%, X5R, 0603; Manufacturer: Kemet; Polarized: N; CompType: Capacitor; Value: 1uF; U/M: EA; Cap_F: 0.000001; Tolerance_%: 10; Value1: Unknown; VDC_V: 16; Value2: 16V; TaMin_C: -55; TaMax_C: 85
J14 J16 = TSW-104-07-G-S: Header, 100mil, 4x1, Gold, TH; Manufacturer: Samtec; SymbolCreator: a0412235; U/M: EA
L31-L33 = BK2125HS102-T: Ferrite Bead, 1000 ohm @ 100 MHz, 0.3 A, 0805; Manufacturer: Taiyo Yuden; Imax_A: 0.3; DCR_ohm: 0.4; Value1: 0.4 ohm; Value2: 0.3A; ZTyp@100MHz_Ohm: 1000
R56 R57 R84 R85 = CRCW04024K70JNED: RES, 4.7 k, 5%, 0.063 W, 0402; Manufacturer: Vishay-Dale; CompType: Resistor; Value: 4.7k; Res_ohm: 4700; Value_Code: 4k70; Tolerance_%: 5; Power_W: 0.063; Value2: 0.063W; VDC_V: 50; TempCo: 200 ppm/C; EIA_Code: E24; U/M: EA
R58-R61 R63 R65-R67 R72 R75 R76 R82 R83 R133 R134 = CRCW040210K0JNED: RES, 10 k, 5%, 0.063 W, 0402; Manufacturer: Vishay-Dale; CompType: Resistor; Value: 10k; Res_ohm: 10000; Value_Code: 10k0; Tolerance_%: 5; Power_W: 0.063; Value2: 0.063W; VDC_V: 50; TempCo: 200 ppm/C; EIA_Code: E24; U/M: EA
R62 R77 R80 R81 = CRCW04020000Z0ED: RES, 0, 5%, 0.063 W, 0402; Manufacturer: Vishay-Dale; CompType: Resistor; Value: 0; Value_Code: 0000; Tolerance_%: 5; Power_W: 0.063; Value2: 0.063W; VDC_V: 50; TempCo: 200 ppm/C; EIA_Code: E24; U/M: EA
R64 R68 = CRCW04022K20JNED: RES, 2.2 k, 5%, 0.063 W, 0402; Manufacturer: Vishay-Dale; CompType: Resistor; Value: 2.2k; Res_ohm: 2200; Value_Code: 2k20; Tolerance_%: 5; Power_W: 0.063; Value2: 0.063W; VDC_V: 50; TempCo: 200 ppm/C; EIA_Code: E24; U/M: EA
R69-R71 R73 = CRCW040233R0JNED: RES, 33, 5%, 0.063 W, 0402; Manufacturer: Vishay-Dale; CompType: Resistor; Value: 33; Value_Code: 33R0; Tolerance_%: 5; Power_W: 0.063; Value2: 0.063W; VDC_V: 50; TempCo: 200 ppm/C; EIA_Code: E24; U/M: EA
R78 = ERJ-2GE0R00X: as R52 on sheet Deserializer
R79 R157 R158 = CRCW04021M00JNED: RES, 1.0 M, 5%, 0.063 W, 0402; Manufacturer: Vishay-Dale; CompType: Resistor; Value: 1.0Meg; Res_ohm: 1000000; Value_Code: 1M00; Tolerance_%: 5; Power_W: 0.063; Value2: 0.063W; VDC_V: 50; TempCo: 200 ppm/C; EIA_Code: E24; U/M: EA
R136 = CRCW08050000Z0EA: Res, Chip, 0E, 1/8W, JUMP, 0805; Manufacturer: Vishay-Dale; CompType: Resistor; Value_Code: 0000; Tolerance_%: 5; Value1: 5%; Power_W: 0.125; Value2: 0.125W; VDC_V: 150; TempCo: 200 ppm/C; EIA_Code: E24; U/M: EA; EN: 101-1-03582; Mfg: VISHAY
R159 = CRCW0402100RFKED: as R51 on sheet Deserializer
TP18-TP20 = 5015: Test Point, Miniature, SMT; Manufacturer: Keystone; CompType: Test Point Loop; U/M: EA
TP33-TP41 = PogoPad: Pad for Pogo Pin Connector; SymbolCreator: codlsc
U8 = OV00490-B00G-1A-Z: Companion ISP processor, BGA100; Manufacturer: OmniVision Technologies; SymbolCreator: a0412235
U10 = W25Q128FVSIG: 3V 128M-bit Serial Flash Memory With Dual SPI&QPI, SO-8; Manufacturer: Winbond; SymbolCreator: a0799628
Y2 = ABM10-24.576MHZ-E20-T: Crystal, 24.576MHz, 10pF, SMD; Manufacturer: Abracon Corportation; SymbolCreator: a0412235; U/M: EA; TaMin_C: -20; TaMax_C: 70; Frequency Stability: ±20ppm

## Sheet OV490_2.SchDoc: OV490_2
size 431 x 279 mm; Date: Not shown in title block; ApprovedBy: Not shown in title block; CheckedBy: Not shown in title block; Author: Not shown in title block; CompanyName: Not shown in title block; DrawnBy: Brian Shaffer; Engineer: Not shown in title block; Organization: Not shown in title block; Address1: Not shown in title block; Address2: Not shown in title block; Address3: Not shown in title block; Address4: Not shown in title block; DocumentNumber: 7; Revision: Use project parameter SCH_Rev; SheetNumber: 7; SheetTotal: 10; PageSetup: Record=PageOptions¦CenterHorizontal=True¦CenterVertical=True¦PrintScale=1.00¦XCorrection=1.00¦YCorrection=1.00¦PrintKind=0¦BorderSize=5000000¦LeftOffset=0¦BottomOffset=0¦Orientation=2¦PaperLength=1000¦PaperWidth=1000¦Scale=100¦PaperSource=15¦PrintQuality=600¦MediaType=1¦DitherType=10¦PaperKind=Letter¦PrintScaleMode=1
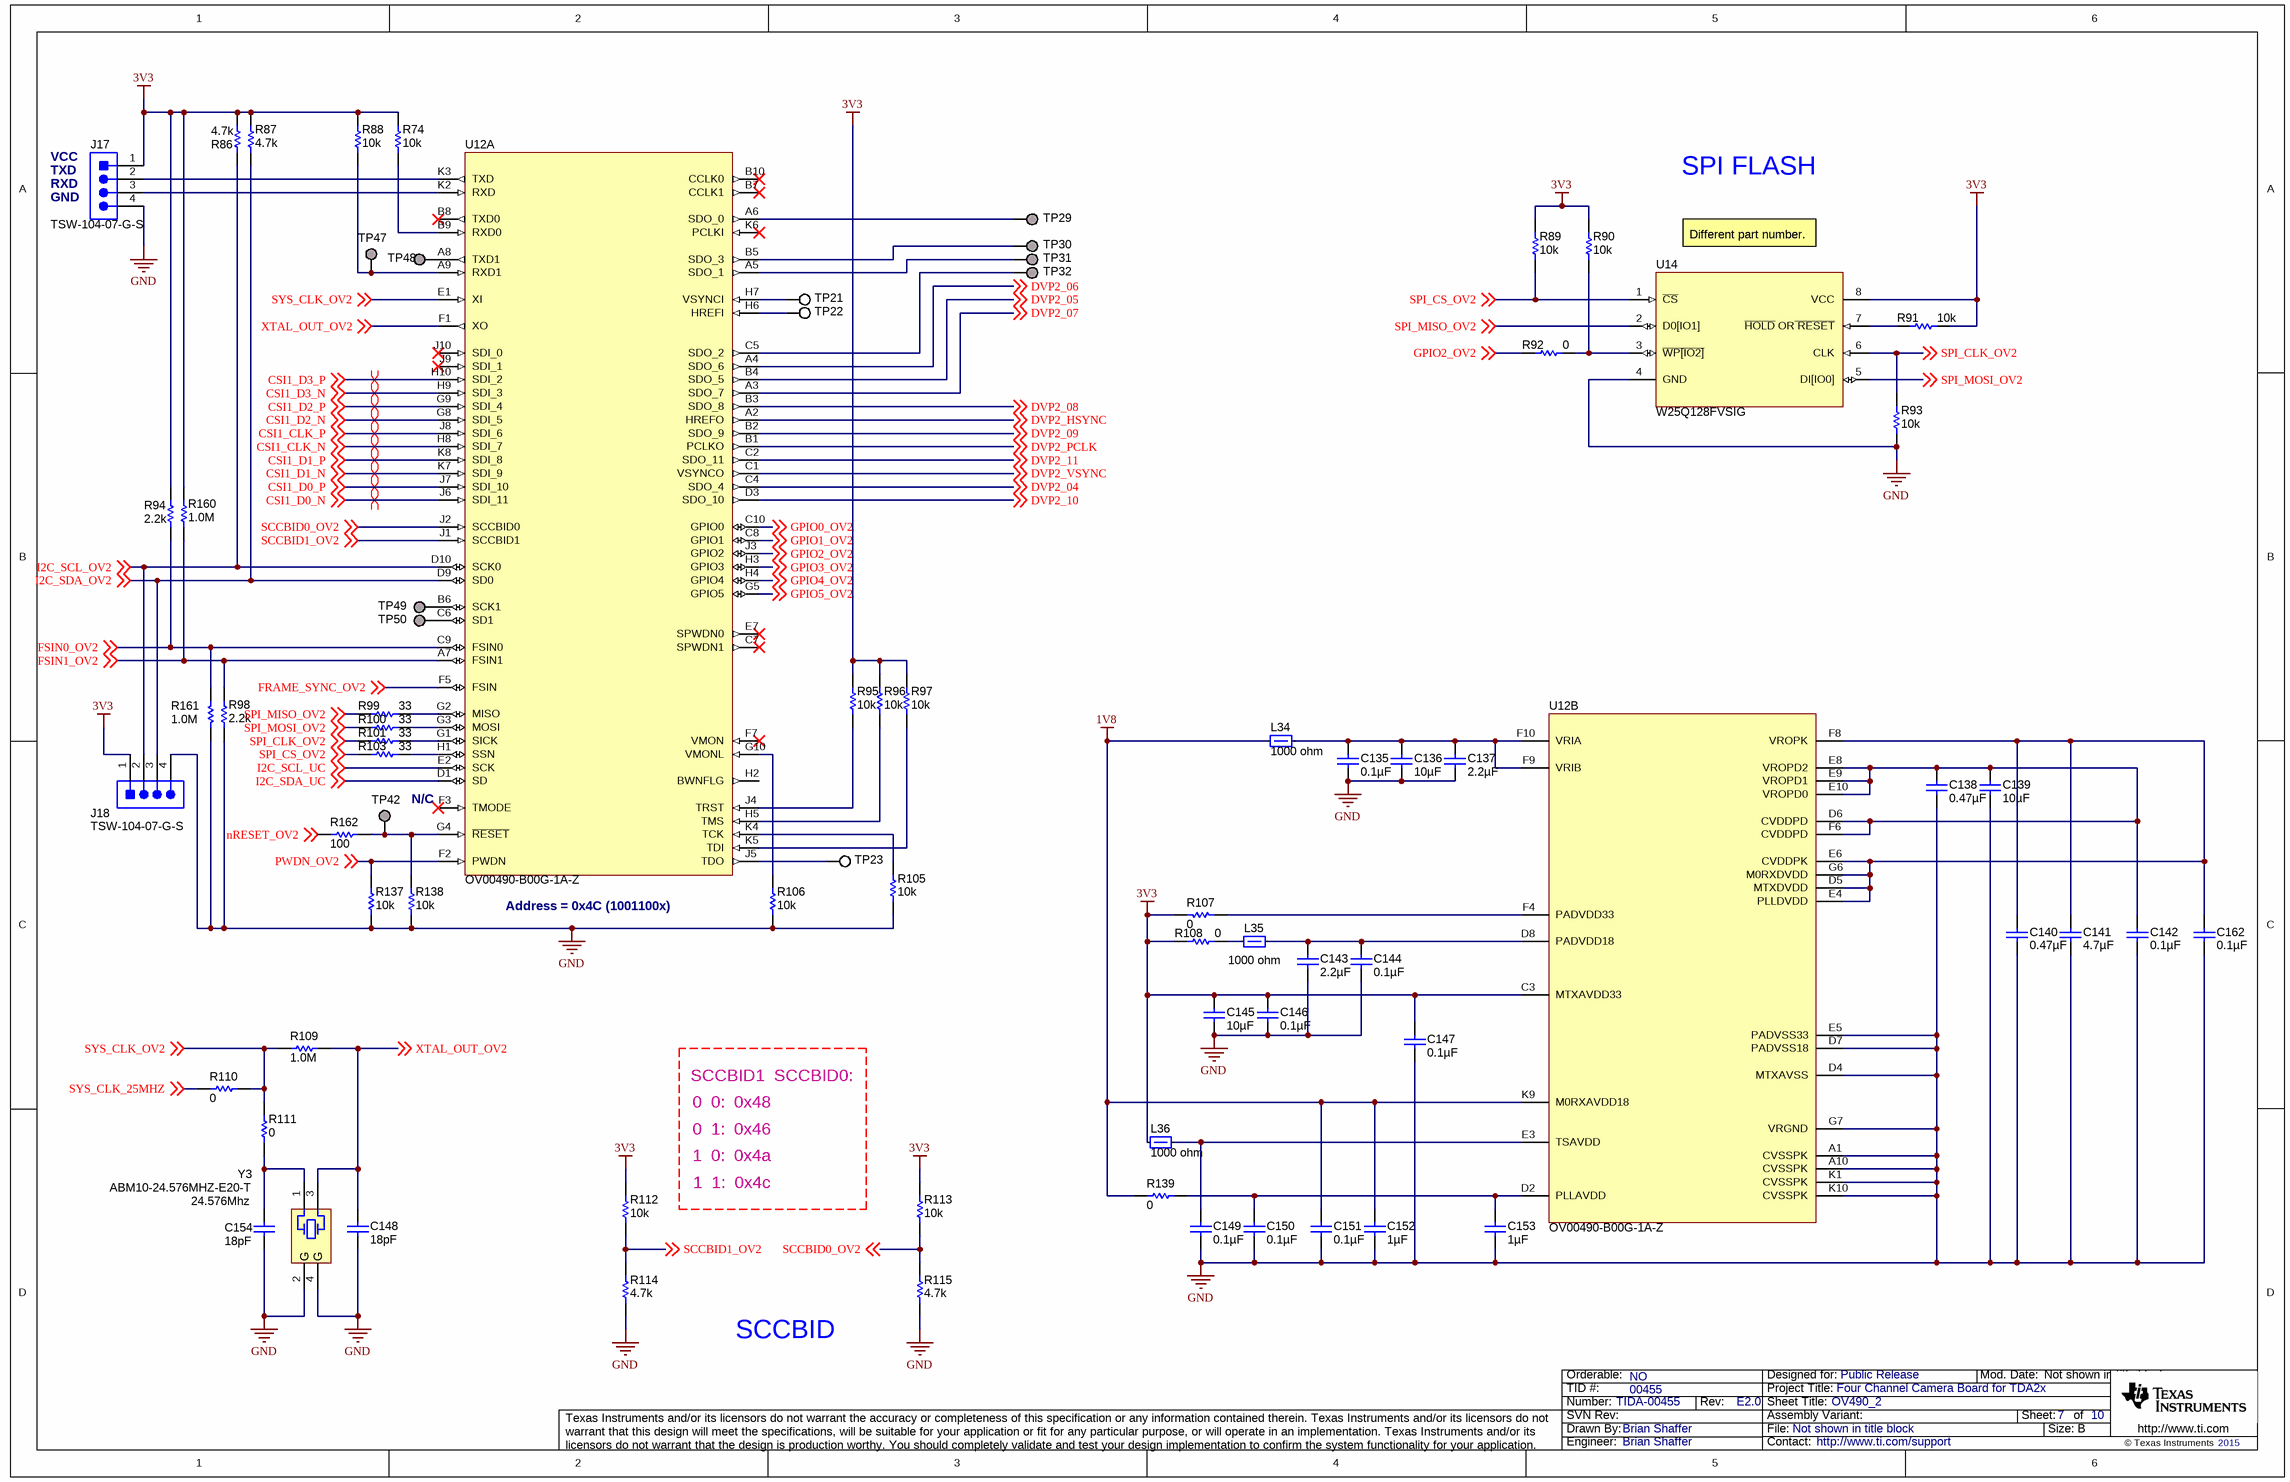
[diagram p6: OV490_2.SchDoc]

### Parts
C135  ValueDisplayed: 0.1µF  [0402]  (hidden comment: C1005X7R1H104K050BB)
C136  ValueDisplayed: 10µF  [0805]  (hidden comment: C2012X7R0J106M125AB)
C137  ValueDisplayed: 2.2µF  [0603]  (hidden comment: C0603C225M8PACTU)
C138  ValueDisplayed: 0.47µF  [0402]  (hidden comment: C1005X5R1A474K050BB)
C139  ValueDisplayed: 10µF  [0805]  (hidden comment: C2012X7R0J106M125AB)
C140  ValueDisplayed: 0.47µF  [0402]  (hidden comment: C1005X5R1A474K050BB)
C141  ValueDisplayed: 4.7µF  [0402]  (hidden comment: C1005X5R1A475K050BC)
C142  ValueDisplayed: 0.1µF  [0402]  (hidden comment: C1005X7R1H104K050BB)
C143  ValueDisplayed: 2.2µF  [0805]  (hidden comment: C2012X5R1A225K/0.85)
C144  ValueDisplayed: 0.1µF  [0402]  (hidden comment: C1005X7R1H104K050BB)
C145  ValueDisplayed: 10µF  [0805]  (hidden comment: C2012X7R0J106M125AB)
C146  ValueDisplayed: 0.1µF  [0402]  (hidden comment: C1005X7R1H104K050BB)
C147  ValueDisplayed: 0.1µF  [0402]  (hidden comment: C1005X7R1H104K050BB)
C148  ValueDisplayed: 18pF  [0603]  (hidden comment: GRM1885C2A180JA01D)
C149  ValueDisplayed: 0.1µF  [0402]  (hidden comment: C1005X7R1H104K050BB)
C150  ValueDisplayed: 0.1µF  [0402]  (hidden comment: C1005X7R1H104K050BB)
C151  ValueDisplayed: 0.1µF  [0402]  (hidden comment: C1005X7R1H104K050BB)
C152  ValueDisplayed: 1µF  [0603]  (hidden comment: C0603C105K4PACTU)
C153  ValueDisplayed: 1µF  [0603]  (hidden comment: C0603C105K4PACTU)
C154  ValueDisplayed: 18pF  [0603]  (hidden comment: GRM1885C2A180JA01D)
C162  ValueDisplayed: 0.1µF  [0402]  (hidden comment: C1005X7R1H104K050BB)
J17  TSW-104-07-G-S  [TSW-104-07-G-S]
J18  TSW-104-07-G-S  [TSW-104-07-G-S]
L34  value 1000 ohm  [0805_HV]  (hidden comment: BK2125HS102-T)
L35  value 1000 ohm  [0805_HV]  (hidden comment: BK2125HS102-T)
L36  value 1000 ohm  [0805_HV]  (hidden comment: BK2125HS102-T)
R74  ValueDisplayed: 10k  [0402]  (hidden comment: CRCW040210K0JNED)
R86  ValueDisplayed: 4.7k  [0402]  (hidden comment: CRCW04024K70JNED)
R87  ValueDisplayed: 4.7k  [0402]  (hidden comment: CRCW04024K70JNED)
R88  ValueDisplayed: 10k  [0402]  (hidden comment: CRCW040210K0JNED)
R89  ValueDisplayed: 10k  [0402]  (hidden comment: CRCW040210K0JNED)
R90  ValueDisplayed: 10k  [0402]  (hidden comment: CRCW040210K0JNED)
R91  ValueDisplayed: 10k  [0402]  (hidden comment: CRCW040210K0JNED)
R92  ValueDisplayed: 0  [0402]  (hidden comment: CRCW04020000Z0ED)
R93  ValueDisplayed: 10k  [0402]  (hidden comment: CRCW040210K0JNED)
R94  ValueDisplayed: 2.2k  [0402]  (hidden comment: CRCW04022K20JNED)
R95  ValueDisplayed: 10k  [0402]  (hidden comment: CRCW040210K0JNED)
R96  ValueDisplayed: 10k  [0402]  (hidden comment: CRCW040210K0JNED)
R97  ValueDisplayed: 10k  [0402]  (hidden comment: CRCW040210K0JNED)
R98  ValueDisplayed: 2.2k  [0402]  (hidden comment: CRCW04022K20JNED)
R99  ValueDisplayed: 33  [0402]  (hidden comment: CRCW040233R0JNED)
R100  ValueDisplayed: 33  [0402]  (hidden comment: CRCW040233R0JNED)
R101  ValueDisplayed: 33  [0402]  (hidden comment: CRCW040233R0JNED)
R103  ValueDisplayed: 33  [0402]  (hidden comment: CRCW040233R0JNED)
R105  ValueDisplayed: 10k  [0402]  (hidden comment: CRCW040210K0JNED)
R106  ValueDisplayed: 10k  [0402]  (hidden comment: CRCW040210K0JNED)
R107  ValueDisplayed: 0  [0402]  (hidden comment: CRCW04020000Z0ED)
R108  value 0  [0402]  (hidden comment: ERJ-2GE0R00X)
R109  ValueDisplayed: 1.0M  [0402]  (hidden comment: CRCW04021M00JNED)
R110  ValueDisplayed: 0  [0402]  (hidden comment: CRCW04020000Z0ED)
R111  ValueDisplayed: 0  [0402]  (hidden comment: CRCW04020000Z0ED)
R112  ValueDisplayed: 10k  [0402]  (hidden comment: CRCW040210K0JNED)
R113  ValueDisplayed: 10k  [0402]  (hidden comment: CRCW040210K0JNED)
R114  ValueDisplayed: 4.7k  [0402]  (hidden comment: CRCW04024K70JNED)
R115  ValueDisplayed: 4.7k  [0402]  (hidden comment: CRCW04024K70JNED)
R137  ValueDisplayed: 10k  [0402]  (hidden comment: CRCW040210K0JNED)
R138  ValueDisplayed: 10k  [0402]  (hidden comment: CRCW040210K0JNED)
R139  value 0  [0805_HV]  (hidden comment: CRCW08050000Z0EA)
R160  ValueDisplayed: 1.0M  [0402]  (hidden comment: CRCW04021M00JNED)
R161  ValueDisplayed: 1.0M  [0402]  (hidden comment: CRCW04021M00JNED)
R162  value 100  [0402]  (hidden comment: CRCW0402100RFKED)
TP21  5015  [Testpoint_Keystone_Miniature]  (value not drawn)
TP22  5015  [Testpoint_Keystone_Miniature]  (value not drawn)
TP23  5015  [Testpoint_Keystone_Miniature]  (value not drawn)
TP29  Pogo Pad  [PogoPad]  (value not drawn)  (no BOM)
TP30  Pogo Pad  [PogoPad]  (value not drawn)  (no BOM)
TP31  Pogo Pad  [PogoPad]  (value not drawn)  (no BOM)
TP32  Pogo Pad  [PogoPad]  (value not drawn)  (no BOM)
TP42  Pogo Pad  [PogoPad]  (value not drawn)  (no BOM)
TP47  Pogo Pad  [PogoPad]  (value not drawn)  (no BOM)
TP48  Pogo Pad  [PogoPad]  (value not drawn)  (no BOM)
TP49  Pogo Pad  [PogoPad]  (value not drawn)  (no BOM)
TP50  Pogo Pad  [PogoPad]  (value not drawn)  (no BOM)
U12  OV00490-B00G-1A-Z  [OVT_OV490]  (parts A,B of 2)
U14  W25Q128FVSIG  [SOIC127P800X216-8N]
Y3  ABM10-24.576MHZ-E20-T  Frequency: 24.576Mhz  [XTAL_ABM10]

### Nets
1V8: C151.1 C152.2 L34.2 R139.1 U12.K9(M0RXAVDD18)
3V3: C145.1 C146.1 C147.2 J17.1 J18.1 L36.2 R74.2 R86.2 R87.2 R88.2 R89.2 R90.2 R91.1 R94.2 R95.2 R96.2 R97.2 R107.2 R108.1 R112.2 R113.2 R160.2 U12.C3(MTXAVDD33) U14.8(VCC)
GND: C135.2 C136.2 C137.2 C138.1 C139.1 C140.1 C141.1 C142.1 C143.1 C144.1 C145.2 C146.2 C147.1 C148.2 C149.2 C150.2 C151.2 C152.1 C153.1 C154.2 C162.1 J17.4 J18.4 R93.1 R98.1 R105.1 R106.1 R114.1 R115.1 R137.1 R138.1 R161.2 U12.A1(CVSSPK) U12.A10(CVSSPK) U12.D4(MTXAVSS) U12.D7(PADVSS18) U12.E5(PADVSS33) U12.G7(VRGND) U12.K1(CVSSPK) U12.K10(CVSSPK) U14.4(GND) Y3.2(GND) Y3.4(GND)
CSI1_CLK_N: U12.H8(SDI_7) ; off-sheet CSI1_CLK_N
CSI1_CLK_P: U12.J8(SDI_6) ; off-sheet CSI1_CLK_P
CSI1_D0_N: U12.J6(SDI_11) ; off-sheet CSI1_D0_N
CSI1_D0_P: U12.J7(SDI_10) ; off-sheet CSI1_D0_P
CSI1_D1_N: U12.K7(SDI_9) ; off-sheet CSI1_D1_N
CSI1_D1_P: U12.K8(SDI_8) ; off-sheet CSI1_D1_P
CSI1_D2_N: U12.G8(SDI_5) ; off-sheet CSI1_D2_N
CSI1_D2_P: U12.G9(SDI_4) ; off-sheet CSI1_D2_P
CSI1_D3_N: U12.H9(SDI_3) ; off-sheet CSI1_D3_N
CSI1_D3_P: U12.H10(SDI_2) ; off-sheet CSI1_D3_P
DVP2_04: U12.C4(SDO_4) ; off-sheet DVP2_04
DVP2_05: U12.B4(SDO_5) ; off-sheet DVP2_05
DVP2_06: U12.A4(SDO_6) ; off-sheet DVP2_06
DVP2_07: U12.A3(SDO_7) ; off-sheet DVP2_07
DVP2_08: U12.B3(SDO_8) ; off-sheet DVP2_08
DVP2_09: U12.B2(SDO_9) ; off-sheet DVP2_09
DVP2_10: U12.D3(SDO_10) ; off-sheet DVP2_10
DVP2_11: U12.C2(SDO_11) ; off-sheet DVP2_11
DVP2_HSYNC: U12.A2(HREFO) ; off-sheet DVP2_HSYNC
DVP2_PCLK: U12.B1(PCLKO) ; off-sheet DVP2_PCLK
DVP2_VSYNC: U12.C1(VSYNCO) ; off-sheet DVP2_VSYNC
FRAME_SYNC_OV2: U12.F5(FSIN) ; off-sheet FRAME_SYNC_OV2
FSIN0_OV2: R94.1 R161.1 U12.C9(FSIN0) ; off-sheet FSIN0_OV2
FSIN1_OV2: R98.2 R160.1 U12.A7(FSIN1) ; off-sheet FSIN1_OV2
GPIO0_OV2: U12.C10(GPIO0) ; off-sheet GPIO0_OV2
GPIO1_OV2: U12.C8(GPIO1) ; off-sheet GPIO1_OV2
GPIO2_OV2: R92.1 U12.J3(GPIO2) ; off-sheet GPIO2_OV2
GPIO3_OV2: U12.H3(GPIO3) ; off-sheet GPIO3_OV2
GPIO4_OV2: U12.H4(GPIO4) ; off-sheet GPIO4_OV2
GPIO5_OV2: U12.G5(GPIO5) ; off-sheet GPIO5_OV2
I2C_SCL_OV2: J18.2 R86.1 U12.D10(SCK0) ; off-sheet I2C_SCL_OV2
I2C_SCL_UC: U12.E2(SCK) ; off-sheet I2C_SCL_UC
I2C_SDA_OV2: J18.3 R87.1 U12.D9(SD0) ; off-sheet I2C_SDA_OV2
I2C_SDA_UC: U12.D1(SD) ; off-sheet I2C_SDA_UC
nRESET_OV2: R162.2 ; off-sheet nRESET_OV2
PWDN_OV2: R137.2 U12.F2(PWDN) ; off-sheet PWDN_OV2
SCCBID0_OV2: R113.1 R115.2 U12.J2(SCCBID0) ; off-sheet SCCBID0_OV2
SCCBID1_OV2: R112.1 R114.2 U12.J1(SCCBID1) ; off-sheet SCCBID1_OV2
SPI_CLK_OV2: R93.2 R101.1 U14.6(CLK) ; off-sheet SPI_CLK_OV2
SPI_CS_OV2: R89.1 R103.1 U14.1(~{CS}) ; off-sheet SPI_CS_OV2
SPI_MISO_OV2: R99.1 U14.2(D0[IO1]) ; off-sheet SPI_MISO_OV2
SPI_MOSI_OV2: R100.1 U14.5(DI[IO0]) ; off-sheet SPI_MOSI_OV2
SYS_CLK_25MHZ: R110.1 ; off-sheet SYS_CLK_25MHZ
SYS_CLK_OV2: R109.1 R110.2 R111.2 U12.E1(XI) ; off-sheet SYS_CLK_OV2
XTAL_OUT_OV2: C148.1 R109.2 U12.F1(XO) Y3.3 ; off-sheet XTAL_OUT_OV2
NetC135_1: C135.1 C136.1 C137.1 L34.1 U12.F9(VRIB) U12.F10(VRIA)
NetC138_2: C138.2 C139.2 C142.2 U12.D6(CVDDPD) U12.E8(VROPD2) U12.E9(VROPD1) U12.E10(VROPD0) U12.F6(CVDDPD)
NetC140_2: C140.2 C141.2 C162.2 U12.D5(MTXDVDD) U12.E4(PLLDVDD) U12.E6(CVDDPK) U12.F8(VROPK) U12.G6(M0RXDVDD)
NetC143_2: C143.2 C144.2 L35.1 U12.D8(PADVDD18)
NetC149_1: C149.1 L36.1 U12.E3(TSAVDD)
NetC150_1: C150.1 C153.2 R139.2 U12.D2(PLLAVDD)
NetC154_1: C154.1 R111.1 Y3.1
NetJ17_2: J17.2 U12.K3(TXD)
NetJ17_3: J17.3 U12.K2(RXD)
NetL35_2: L35.2 R108.2
NetR74_1: R74.1 U12.B9(RXD0)
NetR88_1: R88.1 TP47.1 U12.A9(RXD1)
NetR90_1: R90.1 R92.2 U14.3(~{WP[IO2]})
NetR91_2: R91.2 U14.7(~{HOLD}_OR~{_RESET})
NetR95_1: R95.1 U12.J4(TRST)
NetR96_1: R96.1 U12.H5(TMS)
NetR97_1: R97.1 U12.K5(TDI)
NetR99_2: R99.2 U12.G2(MISO)
NetR100_2: R100.2 U12.G3(MOSI)
NetR101_2: R101.2 U12.G1(SICK)
NetR103_2: R103.2 U12.H1(SSN)
NetR105_2: R105.2 U12.K4(TCK)
NetR106_2: R106.2 U12.G10(VMONL)
NetR107_1: R107.1 U12.F4(PADVDD33)
NetR138_2: R138.2 R162.1 TP42.1 U12.G4(~{RESET})
NetTP21_1: TP21.1 U12.H7(VSYNCI)
NetTP22_1: TP22.1 U12.H6(HREFI)
NetTP23_1: TP23.1 U12.J5(TDO)
NetTP29_1: TP29.1 U12.A6(SDO_0)
NetTP30_1: TP30.1 U12.B5(SDO_3)
NetTP31_1: TP31.1 U12.A5(SDO_1)
NetTP32_1: TP32.1 U12.C5(SDO_2)
NetTP48_1: TP48.1 U12.A8(TXD1)
NetTP49_1: TP49.1 U12.B6(SCK1)
NetTP50_1: TP50.1 U12.C6(SD1)

Not connected (* = marked no-connect by the designer): U12 B7(CCLK1)* B8(TXD0)* B10(CCLK0)* C7(SPWDN1)* E7(SPWDN0)* F3(TMODE)* F7(VMON)* H2(BWNFLG) J9(SDI_1)* J10(SDI_0)* K6(PCLKI)*

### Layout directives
differential pair: CSI1_CLK_N, CSI1_CLK_P, CSI1_D0_N, CSI1_D0_P, CSI1_D1_N, CSI1_D1_P, CSI1_D2_N, CSI1_D2_P, CSI1_D3_N, CSI1_D3_P

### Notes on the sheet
- (near J17) VCC
- SPI FLASH
- (near J17) TXD
- (near J17) RXD
- (near J17) GND
- Different part number.
- N/C
- (near U12) Address = 0x4C (1001100x)
- 0  0:  0x48
- SCCBID1  SCCBID0:
- 0  1:  0x46
- 1  0:  0x4a
- 1  1:  0x4c
- SCCBID

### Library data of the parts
C135 C142 C144 C146 C147 C149-C151 C162 = C1005X7R1H104K050BB: as C115 on sheet OV490_1
C136 C139 C145 = C2012X7R0J106M125AB: as C116 on sheet OV490_1
C137 = C0603C225M8PACTU: as C117 on sheet OV490_1
C138 C140 = C1005X5R1A474K050BB: as C118 on sheet OV490_1
C141 = C1005X5R1A475K050BC: as C121 on sheet OV490_1
C143 = C2012X5R1A225K/0.85: as C123 on sheet OV490_1
C148 C154 = GRM1885C2A180JA01D: as C128 on sheet OV490_1
C152 C153 = C0603C105K4PACTU: as C132 on sheet OV490_1
J17 J18 = TSW-104-07-G-S: as J14 on sheet OV490_1
L34-L36 = BK2125HS102-T: as L31 on sheet OV490_1
R74 R88-R91 R93 R95-R97 R105 R106 R112 R113 R137 R138 = CRCW040210K0JNED: as R58-R61 on sheet OV490_1
R86 R87 R114 R115 = CRCW04024K70JNED: as R56 on sheet OV490_1
R92 R107 R110 R111 = CRCW04020000Z0ED: as R62 on sheet OV490_1
R94 R98 = CRCW04022K20JNED: as R64 on sheet OV490_1
R99-R101 R103 = CRCW040233R0JNED: as R69 on sheet OV490_1
R108 = ERJ-2GE0R00X: as R52 on sheet Deserializer
R109 R160 R161 = CRCW04021M00JNED: as R79 on sheet OV490_1
R139 = CRCW08050000Z0EA: as R136 on sheet OV490_1
R162 = CRCW0402100RFKED: as R51 on sheet Deserializer
TP21-TP23 = 5015: as TP18 on sheet OV490_1
TP29-TP32 TP42 TP47-TP50 = PogoPad: as TP33 on sheet OV490_1
U12 = OV00490-B00G-1A-Z: as U8 on sheet OV490_1
U14 = W25Q128FVSIG: as U10 on sheet OV490_1
Y3 = ABM10-24.576MHZ-E20-T: as Y2 on sheet OV490_1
